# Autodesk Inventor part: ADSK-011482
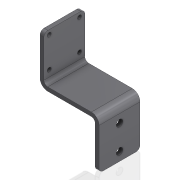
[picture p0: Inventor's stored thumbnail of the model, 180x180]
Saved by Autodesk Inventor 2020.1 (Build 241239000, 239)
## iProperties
Created: 2000-01
Part Number: ADSK-011482
Material: 1.0312 DC05
Description: FSHTPH,FH,CV,057,025,036,090,SUPPORT,TRAY_TRANSFER
Document SubType Name: Tôlerie
Designer: cmcgourin
Density: 1 g/cm^3
Sheet Metal Rule: Stahlblech 1.0312 - DC05 -   6.0 mm
Appearance: Metal-Steel(Polish)
Mass: 83.3915 g
Surface Area: 320.501 cm^2
Volume: 83.3915 cm^3
Flat Pattern Width: 6.35 cm
Flat Pattern Length: 22.2918 cm
Flat Pattern Area: 141.553 cm^2
Sheet Metal Width: 63,500 mm
Sheet Metal Length: 222,918 mm
Sheet Metal Area: 14155,316 mm^2
Control State: 0
Checked Out: False
Master: False
Shininess: 25.0
Length Units: 11269
Angle Units: 11279
Time Units: 11290
Mass Units: 11283
Length Display Precision: 3
Angle Display Precision: 2
Compacted: True
Cutlength: 8.76
Material Desc: FLAT,HRS,0.250 X 02.500
Material_Number: A084330
G_L: 222,9x63,5 mm
Thickness: 6,000 mm
Dimensions: 91,7x146x63,5 mm
Mass: 0,083 kg
Semi finished: Stahlblech 1.0312 - DC05 -   6.0 mm
Density: 0.0
Volumn: 0.0
Area: 0.0
PropertySet Name: Model Information
Author: cmcgourin
Revision Number: -
Title: FSHTPH,FH,CV,057,025,036,090,SUPPORT,TRAY_TRANSFER
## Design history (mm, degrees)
node "Solide1"
  node "Face1"
  node "Flange1"
  node "Flange2"
  node "Corner Round1" dims "d44" = 6.35
  node "Extrusion3" dims "d45" = 25.4, "d46" = 0
  node "Hole3" dims "d47" = 6.35, "d48" = 9.525, "d49" = 6.35, "d50" = 60 deg, "d51" = 19.05, "d52" = 118 deg
node "Plate1" dims "d59" = 6 (= Thickness)
node "Plate2" dims "d40" = 6 (= BendRadius), "d59" = 6 (= Thickness), "MinimumRemnant" = 12 (= 2 x Thickness), "BendReliefWidth" = 6 (= Thickness)
node "Bend1" dims "d40" = 6 (= BendRadius), "d53" = 6 (= BendReliefWidth), "d54" = 3 (= BendReliefDepth), "d55" = 12 (= MinimumRemnant), "d59" = 6 (= Thickness), "SeamGap" = 0.00508, "MinimumRemnant" = 12 (= 2 x Thickness), "BendReliefWidth" = 6 (= Thickness)
node "Plate3" dims "d43" = 6 (= BendRadius), "d59" = 6 (= Thickness), "MinimumRemnant" = 12 (= 2 x Thickness), "BendReliefWidth" = 6 (= Thickness)
node "Bend2" dims "d43" = 6 (= BendRadius), "d56" = 6 (= BendReliefWidth), "d57" = 3 (= BendReliefDepth), "d58" = 12 (= MinimumRemnant), "d59" = 6 (= Thickness), "SeamGap" = 0.00508, "MinimumRemnant" = 12 (= 2 x Thickness), "BendReliefWidth" = 6 (= Thickness)
node "Corps solides"
node "Corps surfaciques"
sketch "Sketch6"
  geometry: L1 (0, 0)-(-76.2, 0); L2 (-76.2, 0)-(-76.2, 63.5); L3 (-76.2, 63.5)-(0, 63.5); L4 (0, 63.5)-(0, 0)
  constraints: 8 end point, 2 parallel, 1 horizontal, 1 perpendicular
  dimensions: "d35" = 63.5 distance of L1.end L2.end; "d36" = 76.2 distance of L2.end L3.end
sketch "Sketch7"
  geometry: L1 (0.35, 0)-(-91.725, 0); L2 (-91.725, 63.5)-(0.35, 63.5); 1 other entity
  constraints: 2 horizontal, 2 vertical alignment
  dimensions: "d38" = 92.075 distance of L1.start L1.end; "d38" = 92.075 distance of L2.end L2.start
sketch "Sketch8"
  geometry: L1 (-0.35, 63.5)-(75.85, 63.5); L2 (75.85, 0)-(-0.35, 0); 1 other entity
  constraints: 2 horizontal, 2 vertical alignment
  dimensions: "d41" = 76.2 distance of L1.start L1.end; "d41" = 76.2 distance of L2.end L2.start
sketch "Sketch9"
  geometry: C1 r 5.159 at (31.75, -12.7) reference; C2 r 5.159 at (31.75, -50.8) reference
sketch "Sketch10"
  geometry: C1 r 2.459 at (55.247, 57) reference; C2 r 2.459 at (8.247, 57) reference; C3 r 2.459 at (8.247, 10) reference; C4 r 2.459 at (55.247, 10) reference
feature "Definition1"
other parameters: "Thickness" = 6 (derived), "BendRadius" = 6 (= Thickness), "BendReliefDepth" = 3 (= 0.5 x Thickness), "CornerReliefSize" = 24 (= 4 x Thickness), "d37" = 6 (= BendRadius), "d39" = 90 deg, "d42" = 90 deg, "TransitionRadius" = 6 (= BendRadius), "TailleRayonJacobi" = 6 (= BendRadius), "TailleJeu" = 6 (= Thickness), "BendRadius" = 6, "BendReliefDepth" = 3, "BendReliefWidth" = 6, "CornerReliefSize" = 24, "MinimumRemnant" = 12, "TailleJeu" = 6, "TailleRayonJacobi" = 6, "Thickness" = 6, "TransitionRadius" = 6
